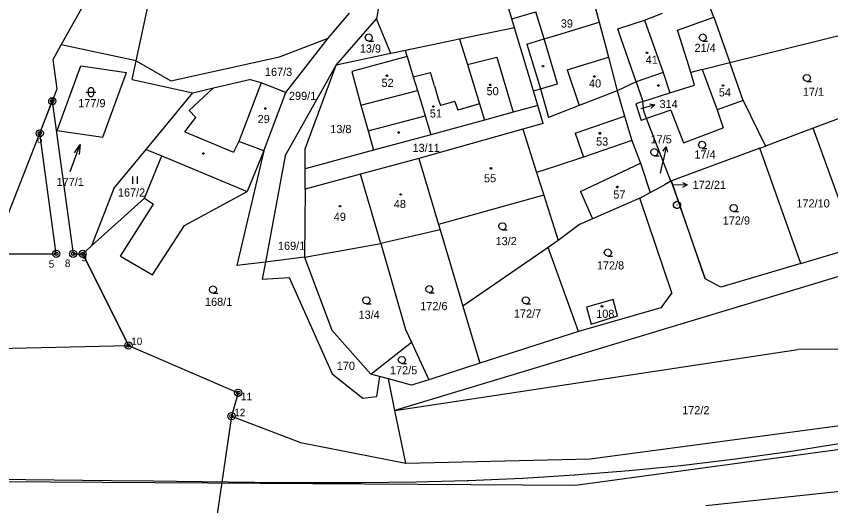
# Model space of a CAD drawing. Extents: x -779723 to -777378, y -1011169 to -1009297.
# Drawn here: x -779247 to -779077.2, y -1010479.3 to -1010377.2 of the extents above; entities that cross this region are included whole.
import ezdxf

# ---------------------------------------------------------------- set-up
doc = ezdxf.new("R2010")
doc.units = 0
for name, color, linetype in [('body', 7, 'Continuous'), ('cisla', 7, 'Continuous'), ('Default', 7, 'Continuous'), ('KN_HRANICE', 7, 'Continuous'), ('KN_KULTURY', 7, 'Continuous'), ('KN_PARCELY', 7, 'Continuous'), ('KN_SLUCKY', 7, 'Continuous'), ('KN_VEDENI', 7, 'Continuous'), ('obvod_stavby', 7, 'Continuous'), ('Železniční svršek', 7, 'Continuous')]:
    doc.layers.add(name, color=color, linetype=linetype)

# ---------------------------------------------------------------- blocks, each defined once
blk = doc.blocks.new('101')
at = {"layer": 'Default'}
blk.add_line((-0.05, 0), (0.05, 0), dxfattribs=at)
blk.add_lwpolyline([(0.19, 0.72), (0.53, 0.53), (0.72, 0.19), (0.72, -0.2), (0.53, -0.54), (0.19, -0.73), (-0.2, -0.73), (-0.54, -0.54), (-0.73, -0.2), (-0.73, 0.19), (-0.54, 0.53), (-0.2, 0.72), (0.19, 0.72)], dxfattribs=at)
blk = doc.blocks.new('304')
at = {"layer": 'Default'}
blk.add_lwpolyline([(0, 0), (-0.38, 0.1), (-0.65, 0.37), (-0.75, 0.74), (-0.65, 1.11), (-0.38, 1.38), (-0.01, 1.48), (0.36, 1.38), (0.63, 1.11), (0.73, 0.73), (0.63, 0.35), (0.36, 0.08), (-0.02, -0.02), (0.98, -0.02)], dxfattribs=at)
blk = doc.blocks.new('306')
at = {"layer": 'Default'}
for p, q in [((-0.5, 1.5), (-0.5, 0)), ((0.5, 0), (0.5, 1.5))]:
    blk.add_line(p, q, dxfattribs=at)
blk = doc.blocks.new('316')
at = {"layer": 'Default'}
for points in [[(-0.5, 1.5), (-0.4, 1.79), (-0.15, 1.97), (0.16, 1.97), (0.41, 1.79), (0.51, 1.5), (0.51, 0.5), (0.41, 0.21), (0.16, 0.03), (-0.15, 0.03), (-0.4, 0.21), (-0.5, 0.5), (-0.5, 1.5)], [(-1, 1), (0.27, 1), (1, 1)]]:
    blk.add_lwpolyline(points, dxfattribs=at)
blk = doc.blocks.new('NAHRADNI_SYMBOL')
at = {"layer": 'Default'}
blk.add_lwpolyline([(0.09, 0.15), (0.18, 0), (0.09, -0.15), (-0.09, -0.15), (-0.18, 0), (-0.09, 0.15), (0.09, 0.15)], dxfattribs=at)
blk = doc.blocks.new('802')
at = {"layer": 'Default'}
blk.add_line((-3, 0), (3, 0), dxfattribs=at)
blk.add_lwpolyline([(1, 0.5), (3, 0), (1, -0.5)], dxfattribs=at)
blk = doc.blocks.new('10292')
at = {"layer": 'Default'}
blk.add_line((0, 3), (0, 0), dxfattribs=at)
blk.add_lwpolyline([(-0.5, 2), (0, 3), (0.5, 2)], dxfattribs=at)
blk = doc.blocks.new('402')
at = {"layer": 'Default'}
blk.add_lwpolyline([(0.09, 0.15), (0.18, 0), (0.09, -0.15), (-0.09, -0.15), (-0.18, 0), (-0.09, 0.15), (0.09, 0.15)], dxfattribs=at)

msp = doc.modelspace()

# ---------------------------------------------------------------- linework, layer by layer
at = {"layer": 'body'}
for p, q in [((-779239.48, -1010394.92), (-779239.48, -1010394.92)), ((-779242.1, -1010401.61), (-779242.1, -1010401.61)), ((-779238.66, -1010426.74), (-779238.66, -1010426.74)), ((-779235.13, -1010426.74), (-779235.13, -1010426.74)), ((-779233.15, -1010426.74), (-779233.15, -1010426.74)), ((-779223.61, -1010445.86), (-779223.61, -1010445.86)), ((-779200.73, -1010455.74), (-779200.73, -1010455.74)), ((-779202.13, -1010460.62), (-779202.13, -1010460.62))]:
    msp.add_line(p, q, dxfattribs=at)
for centre, radius in [((-779239.48, -1010394.92), 0.75), ((-779239.48, -1010394.92), 0.35), ((-779242.1, -1010401.61), 0.75), ((-779242.1, -1010401.61), 0.35), ((-779238.66, -1010426.74), 0.75), ((-779235.13, -1010426.74), 0.75), ((-779233.15, -1010426.74), 0.75), ((-779238.66, -1010426.74), 0.35), ((-779235.13, -1010426.74), 0.35), ((-779233.15, -1010426.74), 0.35), ((-779223.61, -1010445.86), 0.75), ((-779223.61, -1010445.86), 0.35), ((-779200.73, -1010455.74), 0.75), ((-779200.73, -1010455.74), 0.35), ((-779202.13, -1010460.62), 0.75), ((-779202.13, -1010460.62), 0.35)]:
    msp.add_circle(centre, radius, dxfattribs=at)
at = {"layer": 'KN_HRANICE'}
for p, q in [((-779143.7, -1010377.71), (-779148.14, -1010362.87)), ((-779237.61, -1010383.13), (-779227.1, -1010364.33)), ((-779222.02, -1010386.49), (-779217.76, -1010366.81)), ((-779170.69, -1010370.7), (-779171.88, -1010377.7)), ((-779126.96, -1010372.9), (-779125.49, -1010378.42)), ((-779101.55, -1010377.4), (-779102.69, -1010374.53)), ((-779181.94, -1010381.76), (-779177.51, -1010376.54)), ((-779143.7, -1010377.71), (-779138.68, -1010376.27)), ((-779116, -1010377.97), (-779112.28, -1010376.55)), ((-779180.32, -1010387.37), (-779171.88, -1010377.7)), ((-779168.93, -1010384.98), (-779171.88, -1010377.7)), ((-779143.14, -1010379.58), (-779143.7, -1010377.71)), ((-779134.12, -1010381.07), (-779125.49, -1010378.42)), ((-779125.49, -1010378.42), (-779124.04, -1010383.84)), ((-779121.56, -1010379.84), (-779116, -1010377.97)), ((-779109.18, -1010380.08), (-779101.55, -1010377.4)), ((-779101.55, -1010377.4), (-779098.22, -1010386.86)), ((-779143.14, -1010379.58), (-779154.57, -1010381.98)), ((-779139.2, -1010392.75), (-779143.14, -1010379.58)), ((-779120.97, -1010381.67), (-779121.56, -1010379.84)), ((-779107.15, -1010386.41), (-779109.18, -1010380.08)), ((-779098.22, -1010386.86), (-779071.95, -1010380.31)), ((-779192.12, -1010385.68), (-779181.94, -1010381.76)), ((-779190.77, -1010393.08), (-779181.94, -1010381.76)), ((-779154.57, -1010381.98), (-779165.87, -1010384.34)), ((-779154.57, -1010381.98), (-779152.95, -1010387.28)), ((-779140.53, -1010383.03), (-779136.94, -1010381.93)), ((-779136.94, -1010381.93), (-779134.12, -1010381.07)), ((-779117.8, -1010390.87), (-779120.97, -1010381.67)), ((-779239.31, -1010386.18), (-779237.61, -1010383.13)), ((-779222.02, -1010386.49), (-779237.61, -1010383.13)), ((-779140.53, -1010383.03), (-779137.7, -1010392.32)), ((-779124.04, -1010383.84), (-779123.54, -1010385.7)), ((-779168.93, -1010384.98), (-779180.32, -1010387.37)), ((-779165.53, -1010385.55), (-779177.07, -1010388.7)), ((-779165.87, -1010384.34), (-779168.93, -1010384.98)), ((-779165.53, -1010385.55), (-779165.87, -1010384.34)), ((-779165.53, -1010385.55), (-779164.23, -1010389.85)), ((-779238.48, -1010392.35), (-779239.31, -1010386.18)), ((-779222.86, -1010390.35), (-779222.02, -1010386.49)), ((-779222.02, -1010386.49), (-779214.8, -1010390.67)), ((-779214.8, -1010390.67), (-779192.12, -1010385.68)), ((-779152.95, -1010387.28), (-779150.45, -1010395.45)), ((-779123.54, -1010385.7), (-779121.71, -1010392.72)), ((-779106.38, -1010388.93), (-779107.15, -1010386.41)), ((-779103.99, -1010388.3), (-779098.22, -1010386.86)), ((-779095.45, -1010394.78), (-779098.22, -1010386.86)), ((-779238.5, -1010401), (-779233.52, -1010387.55)), ((-779233.52, -1010387.55), (-779224.02, -1010388.94)), ((-779228.95, -1010402.41), (-779224.02, -1010388.94)), ((-779190.91, -1010406.29), (-779180.32, -1010387.37)), ((-779186.74, -1010404.87), (-779180.32, -1010387.37)), ((-779177.07, -1010388.7), (-779175.14, -1010395.73)), ((-779103.99, -1010388.3), (-779106.38, -1010388.93)), ((-779105.6, -1010391.53), (-779106.38, -1010388.93)), ((-779222.86, -1010390.35), (-779210.18, -1010393.14)), ((-779205.88, -1010392.14), (-779198.36, -1010390.38)), ((-779195.92, -1010391.11), (-779198.36, -1010390.38)), ((-779164.23, -1010389.85), (-779163.38, -1010392.66)), ((-779257.31, -1010440.46), (-779238.48, -1010392.35)), ((-779210.18, -1010393.14), (-779205.88, -1010392.14)), ((-779190.77, -1010393.08), (-779195.92, -1010391.11)), ((-779139.2, -1010392.75), (-779137.7, -1010392.32)), ((-779137.7, -1010392.32), (-779136.01, -1010398.29)), ((-779117.8, -1010390.87), (-779121.71, -1010392.72)), ((-779117.8, -1010390.87), (-779116.39, -1010395)), ((-779110.74, -1010393.18), (-779105.6, -1010391.53)), ((-779219.94, -1010404.96), (-779210.18, -1010393.14)), ((-779195.38, -1010405.25), (-779190.77, -1010393.08)), ((-779163.38, -1010392.66), (-779162.54, -1010395.42)), ((-779138.27, -1010395.83), (-779139.2, -1010392.75)), ((-779121.71, -1010392.72), (-779129.66, -1010395.82)), ((-779121.71, -1010392.72), (-779120.21, -1010398.06)), ((-779116.39, -1010395), (-779110.74, -1010393.18)), ((-779175.14, -1010395.73), (-779173.66, -1010401.1)), ((-779162.54, -1010395.42), (-779161.78, -1010397.93)), ((-779150.45, -1010395.45), (-779149.41, -1010398.86)), ((-779129.66, -1010395.82), (-779136.01, -1010398.29)), ((-779116.39, -1010395), (-779117.81, -1010395.46)), ((-779117.81, -1010395.46), (-779116.75, -1010398.9)), ((-779116.19, -1010396.96), (-779116.39, -1010395)), ((-779095.45, -1010394.78), (-779100.91, -1010396.73)), ((-779095.45, -1010394.78), (-779090.81, -1010404.3)), ((-779143.38, -1010397.22), (-779149.41, -1010398.86)), ((-779138.27, -1010395.83), (-779143.38, -1010397.22)), ((-779137.16, -1010399.54), (-779138.27, -1010395.83)), ((-779115.59, -1010398.51), (-779116.19, -1010396.96)), ((-779110.51, -1010396.79), (-779115.59, -1010398.51)), ((-779110.51, -1010396.79), (-779107.93, -1010403.57)), ((-779100.91, -1010396.73), (-779099.61, -1010400.48)), ((-779069.32, -1010396.17), (-779080.88, -1010400.54)), ((-779161.78, -1010397.93), (-779160.58, -1010401.9)), ((-779149.41, -1010398.86), (-779157.03, -1010400.93)), ((-779120.21, -1010398.06), (-779118.64, -1010403.14)), ((-779115.59, -1010398.51), (-779116.75, -1010398.9)), ((-779110.52, -1010411.6), (-779115.59, -1010398.51)), ((-779141.41, -1010400.75), (-779163.08, -1010406.87)), ((-779137.16, -1010399.54), (-779141.41, -1010400.75)), ((-779141.41, -1010400.75), (-779138.52, -1010409.8)), ((-779107.93, -1010403.57), (-779099.61, -1010400.48)), ((-779080.88, -1010400.54), (-779090.81, -1010404.3)), ((-779071.93, -1010425.3), (-779080.88, -1010400.54)), ((-779238.5, -1010401), (-779228.95, -1010402.41)), ((-779173.66, -1010401.1), (-779172.54, -1010405.15)), ((-779160.58, -1010401.9), (-779172.54, -1010405.15)), ((-779157.03, -1010400.93), (-779160.58, -1010401.9)), ((-779118.64, -1010403.14), (-779128.76, -1010406.55)), ((-779118.64, -1010403.14), (-779116.88, -1010407.82)), ((-779091.99, -1010404.73), (-779090.81, -1010404.3)), ((-779226.66, -1010413.11), (-779219.94, -1010404.96)), ((-779219.94, -1010404.96), (-779216.67, -1010406.33)), ((-779195.38, -1010405.25), (-779201, -1010429.21)), ((-779195.38, -1010405.25), (-779198.89, -1010413.78)), ((-779186.75, -1010409.02), (-779186.74, -1010404.87)), ((-779172.54, -1010405.15), (-779186.75, -1010409.02)), ((-779091.99, -1010404.73), (-779110.38, -1010411.52)), ((-779083.42, -1010428.77), (-779091.99, -1010404.73)), ((-779220.25, -1010415.13), (-779216.67, -1010406.33)), ((-779190.91, -1010406.29), (-779195.06, -1010428.47)), ((-779163.08, -1010406.87), (-779175.21, -1010410.13)), ((-779163.08, -1010406.87), (-779158.98, -1010420.63)), ((-779128.76, -1010406.55), (-779134.68, -1010408.52)), ((-779186.75, -1010413.24), (-779186.75, -1010409.02)), ((-779134.68, -1010408.52), (-779138.52, -1010409.8)), ((-779116.88, -1010407.82), (-779114.86, -1010413.95)), ((-779175.21, -1010410.13), (-779186.75, -1010413.24)), ((-779171.02, -1010424.6), (-779175.21, -1010410.13)), ((-779138.52, -1010409.8), (-779137.02, -1010414.51)), ((-779114.86, -1010413.95), (-779111.87, -1010412.33)), ((-779110.52, -1010411.6), (-779111.87, -1010412.33)), ((-779110.52, -1010411.6), (-779110.38, -1010411.52)), ((-779110.52, -1010411.6), (-779110.28, -1010412.21)), ((-779103.35, -1010431.99), (-779110.38, -1010411.52)), ((-779110.28, -1010412.21), (-779103.35, -1010431.99)), ((-779226.66, -1010413.11), (-779231.29, -1010425.07)), ((-779211.9, -1010420.85), (-779198.89, -1010413.78)), ((-779186.75, -1010413.24), (-779186.88, -1010427.45)), ((-779117.03, -1010415.13), (-779114.86, -1010413.95)), ((-779220.25, -1010415.13), (-779231.29, -1010425.07)), ((-779220.25, -1010415.13), (-779218.42, -1010416.38)), ((-779137.02, -1010414.51), (-779158.98, -1010420.63)), ((-779137.02, -1010414.51), (-779134, -1010424)), ((-779117.03, -1010415.13), (-779126.85, -1010419.42)), ((-779110.3, -1010434.92), (-779117.03, -1010415.13)), ((-779225.24, -1010427.24), (-779218.42, -1010416.38)), ((-779126.85, -1010419.42), (-779129.59, -1010420.64)), ((-779218.62, -1010431.11), (-779211.9, -1010420.85)), ((-779158.98, -1010420.63), (-779158.66, -1010421.72)), ((-779129.59, -1010420.64), (-779134, -1010424)), ((-779158.66, -1010421.72), (-779171.02, -1010424.6)), ((-779158.66, -1010421.72), (-779153.92, -1010437.67)), ((-779186.88, -1010427.45), (-779171.02, -1010424.6)), ((-779171.02, -1010424.6), (-779165.83, -1010442.55)), ((-779134, -1010424), (-779136.09, -1010425.43)), ((-779231.29, -1010425.07), (-779233.15, -1010426.74)), ((-779136.09, -1010425.43), (-779153.92, -1010437.67)), ((-779129.76, -1010442.93), (-779136.09, -1010425.43)), ((-779083.42, -1010428.77), (-779071.93, -1010425.3)), ((-779223.61, -1010445.86), (-779233.15, -1010426.74)), ((-779225.24, -1010427.24), (-779218.62, -1010431.11)), ((-779186.88, -1010427.45), (-779195.06, -1010428.47)), ((-779186.88, -1010427.45), (-779181.22, -1010442.66)), ((-779063.54, -1010427.85), (-779168.06, -1010459.43)), ((-779195.06, -1010428.47), (-779201, -1010429.21)), ((-779195.06, -1010428.47), (-779195.73, -1010432.05)), ((-779083.42, -1010428.77), (-779100.12, -1010433.69)), ((-779195.73, -1010432.05), (-779190.11, -1010431.7)), ((-779190.11, -1010431.7), (-779181.17, -1010451.77)), ((-779100.12, -1010433.69), (-779103.35, -1010431.99)), ((-779122.59, -1010436.25), (-779128.15, -1010437.89)), ((-779121.63, -1010439.67), (-779122.59, -1010436.25)), ((-779110.3, -1010434.92), (-779112.61, -1010437.99)), ((-779153.92, -1010437.67), (-779150.37, -1010449.59)), ((-779112.61, -1010437.99), (-779129.76, -1010442.93)), ((-779128.15, -1010437.89), (-779127.13, -1010441.39)), ((-779127.13, -1010441.39), (-779121.63, -1010439.67)), ((-779181.22, -1010442.66), (-779173.08, -1010451.87)), ((-779165.83, -1010442.55), (-779164.63, -1010445.15)), ((-779129.76, -1010442.93), (-779150.37, -1010449.59)), ((-779255.18, -1010446.63), (-779223.61, -1010445.86)), ((-779223.61, -1010445.86), (-779200.73, -1010455.74)), ((-779173.08, -1010451.87), (-779164.63, -1010445.15)), ((-779168.06, -1010459.43), (-779084.08, -1010446.73)), ((-779164.63, -1010445.15), (-779161.01, -1010453.02)), ((-779043.03, -1010446.43), (-779084.08, -1010446.73)), ((-779150.37, -1010449.59), (-779161.01, -1010453.02)), ((-779181.17, -1010451.77), (-779174.76, -1010456.86)), ((-779171.3, -1010452.35), (-779173.08, -1010451.87)), ((-779171.3, -1010452.35), (-779171.87, -1010456.53)), ((-779169.43, -1010452.86), (-779171.3, -1010452.35)), ((-779164.59, -1010454.17), (-779169.43, -1010452.86)), ((-779168.06, -1010459.43), (-779169.43, -1010452.86)), ((-779161.01, -1010453.02), (-779164.59, -1010454.17)), ((-779200.73, -1010455.74), (-779202.13, -1010460.62)), ((-779174.76, -1010456.86), (-779171.87, -1010456.53)), ((-779165.75, -1010470.45), (-779168.06, -1010459.43)), ((-779202.13, -1010460.62), (-779187.71, -1010466.11)), ((-779127.38, -1010469.51), (-779070.54, -1010461.9)), ((-779187.71, -1010466.11), (-779165.75, -1010470.45)), ((-779165.75, -1010470.45), (-779127.38, -1010469.51)), ((-779103.26, -1010479.27), (-779067.56, -1010475.45))]:
    msp.add_line(p, q, dxfattribs=at)
at = {"layer": 'KN_PARCELY'}
msp.add_line((-779112.71, -1010409.91), (-779112.14, -1010407.36), dxfattribs=at)
at = {"layer": 'KN_SLUCKY'}
for p, q in [((-779136.94, -1010381.93), (-779138.68, -1010376.27)), ((-779116, -1010377.97), (-779112.15, -1010388.92)), ((-779134.17, -1010391.31), (-779136.94, -1010381.93)), ((-779152.95, -1010387.28), (-779146.78, -1010385.72)), ((-779146.78, -1010385.72), (-779143.38, -1010397.22)), ((-779132.14, -1010388.34), (-779123.54, -1010385.7)), ((-779164.23, -1010389.85), (-779160.66, -1010388.9)), ((-779159.81, -1010391.73), (-779160.66, -1010388.9)), ((-779132.14, -1010388.34), (-779129.66, -1010395.82)), ((-779112.15, -1010388.92), (-779117.8, -1010390.87)), ((-779112.15, -1010388.92), (-779110.74, -1010393.18)), ((-779103.99, -1010388.3), (-779100.91, -1010396.73)), ((-779210.93, -1010396.85), (-779205.88, -1010392.14)), ((-779195.92, -1010391.11), (-779200.6, -1010403.31)), ((-779159.81, -1010391.73), (-779159.01, -1010394.4)), ((-779137.7, -1010392.32), (-779134.17, -1010391.31)), ((-779175.14, -1010395.73), (-779163.38, -1010392.66)), ((-779159.01, -1010394.4), (-779158.58, -1010395.81)), ((-779155.55, -1010395), (-779158.58, -1010395.81)), ((-779155.55, -1010395), (-779154.97, -1010396.76)), ((-779150.45, -1010395.45), (-779154.97, -1010396.76)), ((-779210.93, -1010396.85), (-779209.53, -1010398.31)), ((-779211.82, -1010401.29), (-779209.53, -1010398.31)), ((-779173.66, -1010401.1), (-779161.78, -1010397.93)), ((-779130.48, -1010401.56), (-779120.21, -1010398.06)), ((-779211.82, -1010401.29), (-779201.69, -1010405.54)), ((-779130.48, -1010401.56), (-779128.76, -1010406.55)), ((-779200.6, -1010403.31), (-779201.69, -1010405.54)), ((-779195.38, -1010405.25), (-779200.6, -1010403.31)), ((-779216.67, -1010406.33), (-779198.89, -1010413.78)), ((-779129.37, -1010413.73), (-779116.88, -1010407.82)), ((-779129.37, -1010413.73), (-779126.85, -1010419.42))]:
    msp.add_line(p, q, dxfattribs=at)
at = {"layer": 'KN_VEDENI'}
for p, q in [((-779130.44, -1010475.03), (-779042.85, -1010463.08)), ((-779395.56, -1010473.38), (-779130.44, -1010475.03))]:
    msp.add_line(p, q, dxfattribs=at)
at = {"layer": 'obvod_stavby'}
msp.add_lwpolyline([(-779249.69, -1010446.5), (-779249.69, -1010426.74), (-779238.66, -1010426.74), (-779242.1, -1010401.61), (-779239.48, -1010394.92), (-779235.13, -1010426.74), (-779233.15, -1010426.74), (-779223.61, -1010445.86), (-779200.73, -1010455.74), (-779202.13, -1010460.62), (-779207.48, -1010497.19), (-779226.1, -1010504.31), (-779235.46, -1010501.42), (-779255.21, -1010502.98), (-779255.18, -1010446.63), (-779249.69, -1010446.5)], dxfattribs=at)
at = {"layer": 'Železniční svršek'}
for p, q in [((-779233.21, -1010474.03), (-779254.8, -1010473.76)), ((-779227.16, -1010474.09), (-779233.21, -1010474.03)), ((-779218.4, -1010474.21), (-779227.16, -1010474.09)), ((-779213.59, -1010474.26), (-779218.4, -1010474.21)), ((-779208.23, -1010474.32), (-779213.59, -1010474.26)), ((-779197.43, -1010474.45), (-779208.23, -1010474.32))]:
    msp.add_line(p, q, dxfattribs=at)
for points in [[(-779075.05, -1010466.31), (-779086.32, -1010468.1)], [(-779086.34, -1010468.1), (-779097.06, -1010469.6)], [(-779097.08, -1010469.6), (-779108.43, -1010470.97)], [(-779119.22, -1010472.04), (-779130.65, -1010472.94)], [(-779108.45, -1010470.97), (-779119.2, -1010472.04)], [(-779141.41, -1010473.61), (-779152.89, -1010474.1)], [(-779130.67, -1010472.95), (-779141.39, -1010473.61)], [(-779186.63, -1010474.52), (-779197.43, -1010474.45)], [(-779175.13, -1010474.5), (-779186.62, -1010474.52)], [(-779163.68, -1010474.37), (-779175.12, -1010474.5)], [(-779152.9, -1010474.1), (-779163.67, -1010474.37)]]:
    msp.add_lwpolyline(points, dxfattribs=at)
for centre, start, end in [((-779086.48, -1010467.11), 277.9522, 279.019), ((-779097.19, -1010468.61), 276.87, 277.9522), ((-779119.3, -1010471.04), 274.5242, 275.6827), ((-779108.55, -1010469.97), 275.6827, 276.87), ((-779141.45, -1010472.61), 272.4303, 273.5338), ((-779130.73, -1010471.95), 273.5338, 274.5242), ((-779186.62, -1010473.52), 269.6447, 270.0598), ((-779175.13, -1010473.5), 270.0598, 270.6655), ((-779163.69, -1010473.37), 270.6655, 271.461), ((-779152.93, -1010473.1), 271.461, 272.4303)]:
    msp.add_arc(centre, 1, start, end, dxfattribs=at)

# ---------------------------------------------------------------- block references
at = {"layer": 'KN_KULTURY'}
for name, p in [('304', (-779173.5, -1010382.36)), ('304', (-779103.87, -1010382.35)), ('402', (-779115.51, -1010384.83)), ('402', (-779137.17, -1010387.58)), ('402', (-779169.73, -1010389.58)), ('402', (-779126.48, -1010389.76)), ('304', (-779082.18, -1010390.79)), ('316', (-779231.41, -1010394)), ('402', (-779148.2, -1010391.5)), ('402', (-779113.16, -1010391.61)), ('402', (-779099.68, -1010391.62)), ('402', (-779195.08, -1010396.43)), ('402', (-779160.04, -1010396.02)), ('402', (-779167.26, -1010401.46)), ('402', (-779125.34, -1010401.62)), ('304', (-779104.01, -1010404.74)), ('402', (-779207.98, -1010405.83)), ('304', (-779113.97, -1010406.29)), ('NAHRADNI_SYMBOL', (-779148.03, -1010408.91)), ('306', (-779222.25, -1010412.13)), ('402', (-779121.72, -1010412.81)), ('NAHRADNI_SYMBOL', (-779166.87, -1010414.38)), ('NAHRADNI_SYMBOL', (-779179.52, -1010416.82)), ('304', (-779097.43, -1010417.92)), ('304', (-779145.67, -1010421.73)), ('304', (-779123.67, -1010427.22)), ('304', (-779205.96, -1010434.93)), ('304', (-779160.89, -1010434.85)), ('304', (-779174, -1010437.19)), ('304', (-779140.75, -1010437.19)), ('402', (-779124.88, -1010437.7)), ('304', (-779166.6, -1010449.62))]:
    msp.add_blockref(name, p, dxfattribs=at)
at = {"layer": 'KN_KULTURY', "rotation": 69.728964}
msp.add_blockref('802', (-779234.7, -1010406.77), dxfattribs=at)
at = {"layer": 'KN_PARCELY'}
for p, rotation in [((-779116.76, -1010396.47), -74.724314), ((-779112.14, -1010407.36), -12.501097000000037), ((-779110.13, -1010412.43), -88.76178)]:
    msp.add_blockref('10292', p, dxfattribs=dict(at, rotation=rotation))
msp.add_blockref('101', (-779109.23, -1010416.55), dxfattribs=at)

# ---------------------------------------------------------------- texts
at = {"layer": 'cisla'}
for s, p in [('  7', (-779241.02, -1010395.83)), ('  6', (-779243.85, -1010403.65)), ('  8', (-779238.02, -1010429.49)), ('  9', (-779234.59, -1010428.29)), ('  5', (-779241.38, -1010429.64)), (' 10', (-779223.61, -1010445.78)), (' 11', (-779200.73, -1010457.29)), (' 12', (-779202.13, -1010460.63))]:
    msp.add_text(s, height=1.552, dxfattribs=at).set_placement(p)
at = {"layer": 'KN_PARCELY'}
for s, height, p in [('39', 1.7, (-779133.47, -1010379.54)), ('13/9', 1.7, (-779175.38, -1010384.77)), ('21/4', 1.7, (-779105.6, -1010384.63)), ('41', 1.7, (-779115.78, -1010387.11)), ('167/3', 1.7, (-779195.16, -1010389.64)), ('52', 1.7, (-779170.85, -1010391.93)), ('40', 1.7, (-779127.6, -1010392.04)), ('50', 1.7, (-779148.95, -1010393.66)), ('54', 1.7, (-779100.54, -1010393.91)), ('17/1', 1.7, (-779083.02, -1010393.78)), ('299/1', 1.7, (-779190.15, -1010394.64)), ('177/9', 1.7, (-779234.08, -1010396.16)), ('314', 1.7, (-779112.9, -1010396.33)), ('51', 1.7, (-779160.79, -1010398.3)), ('314', 0.1, (-779116.75, -1010396.47)), ('29', 1.7, (-779196.68, -1010399.48)), ('13/8', 1.7, (-779181.54, -1010401.57)), ('53', 1.7, (-779126.12, -1010404.16)), ('17/5', 1.7, (-779114.77, -1010403.7)), ('13/11', 1.7, (-779164.39, -1010405.49)), ('17/4', 1.7, (-779105.63, -1010406.87)), ('177/1', 1.7, (-779238.6, -1010412.6)), ('55', 1.7, (-779149.49, -1010411.84)), ('17/5', 0.1, (-779112.69, -1010409.91)), ('172/21', 0.1, (-779110.11, -1010412.43)), ('172/21', 1.7, (-779105.99, -1010413.2)), ('167/2', 1.7, (-779225.81, -1010414.8)), ('57', 1.7, (-779122.53, -1010415.22)), ('48', 1.7, (-779168.29, -1010417.2)), ('172/10', 1.7, (-779084.37, -1010417.07)), ('49', 1.7, (-779180.81, -1010419.88)), ('172/9', 1.7, (-779099.72, -1010420.64)), ('169/1', 1.7, (-779192.44, -1010425.91)), ('13/2', 1.7, (-779147.07, -1010424.94)), ('172/8', 1.7, (-779125.96, -1010430.01)), ('168/1', 1.7, (-779207.65, -1010437.6)), ('172/6', 1.7, (-779162.79, -1010438.51)), ('172/7', 1.7, (-779143.26, -1010440.06)), ('13/4', 1.7, (-779175.64, -1010440.3)), ('108', 1.7, (-779126.1, -1010440.11)), ('170', 1.7, (-779180.18, -1010450.96)), ('172/5', 1.7, (-779169.09, -1010451.9)), ('172/2', 1.7, (-779108.18, -1010460.23))]:
    msp.add_text(s, height=height, dxfattribs=at).set_placement(p)

doc.saveas('drawing.dxf')
